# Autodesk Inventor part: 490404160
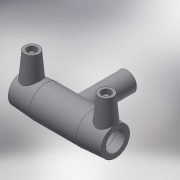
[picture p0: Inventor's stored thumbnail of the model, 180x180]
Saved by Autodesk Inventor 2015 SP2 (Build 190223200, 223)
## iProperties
Created: 2017-06
Part Number: 490404160
Material: Generic
Description: PLASSON TEE 160-160-160
Document SubType Name: Modeling
Designer: KIM
Mass: 57.3761 g
Surface Area: 241.06 cm^2
Volume: 57.3761 cm^3
Density: 1 g/cm^3
Appearance: Default
Author: KIM
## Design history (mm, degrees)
derived "490404.ipt"
feature "Solid1::490404.ipt"
tag "TaggingFeature1"
body "Solid1"
other parameters: "d2" = 208, "d3" = 86, "d5" = 187.2, "d6" = 152, "d8" = 168 deg, "d10" = 34.4, "d11" = 11.46667, "d14" = 17.6296, "d17" = 144, "d19" = 3.52592, "d20" = 168 deg, "d22" = 193.44, "d23" = 208, "d24" = 187.6368, "d25" = 135 deg, "d26" = 308, "d27" = 135 deg, "d29" = 106, "d30" = 15, "d31" = 176, "d34" = 5 deg, "d35" = 15, "d39" = 5 deg, "d40" = 9.6, "d41" = 4.8, "d42" = 6, "d43" = 0, "d45" = 4, "d46" = 14, "d47" = 0, "d48" = -206, "d51" = 0, "d52" = 128, "d54" = 0, "d55" = 187.2, "d56" = 208, "d57" = 154, "d58" = 135 deg, "d59" = 86, "d60" = 86, "d61" = 135 deg, "d62" = 206, "d72" = 200.2, "d73" = 100.1, "d74" = -206, "d75" = 168, "d77" = 0, "d78" = 128, "d80" = 0, "d82" = 102, "d83" = 0, "d84" = 3, "d85" = 0, "d86" = 3, "d87" = 0, "d88" = 24.94, "d89" = 6.235, "d90" = 24.94, "L_1" = 86, "D_" = 208, "A_" = 106, "d_2" = 12, "H_" = 206
